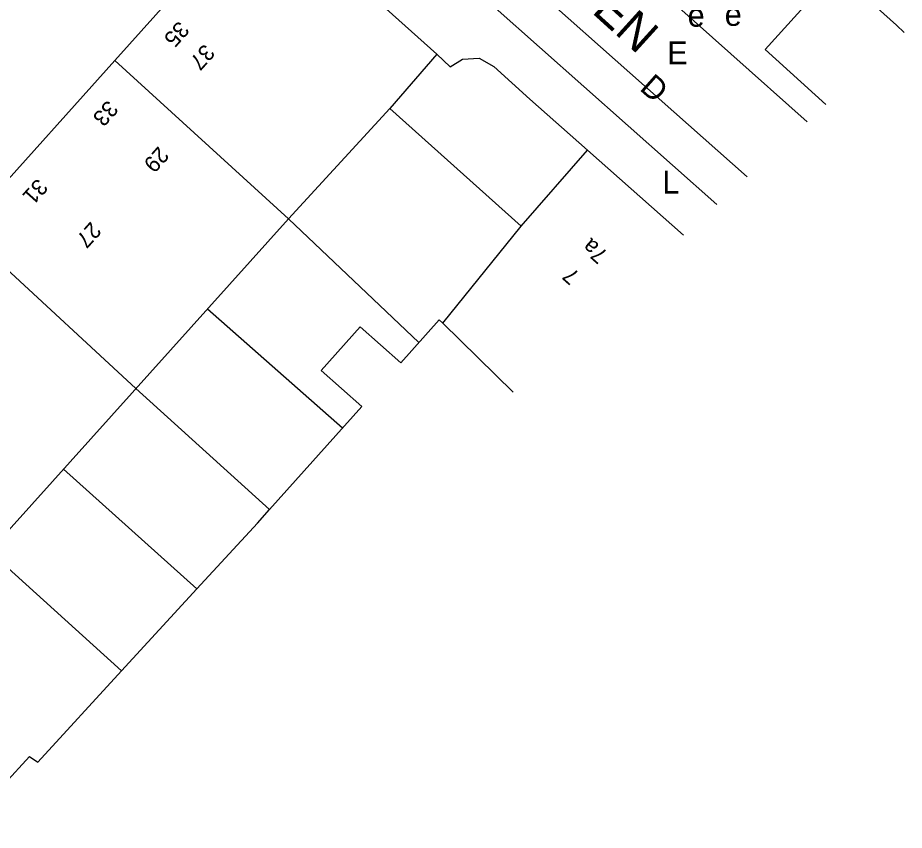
# Model space of a CAD drawing. Extents: x 81617 to 82144, y 454649 to 455150.
# Drawn here: x 81774.65 to 81813.36, y 454705.97 to 454741.45 of the extents above; entities that cross this region are included whole.
import ezdxf

# ---------------------------------------------------------------- set-up
doc = ezdxf.new("R2010")
doc.units = 0
doc.layers.add('B-WE-OG-TOPOGRAFIE-G', color=7, linetype='Continuous')

msp = doc.modelspace()

# ---------------------------------------------------------------- linework, layer by layer
at = {"layer": 'B-WE-OG-TOPOGRAFIE-G'}
for p, q in [((81786.184, 454745.913), (81792.953, 454739.866)), ((81778.882, 454739.59), (81786.471, 454732.664)), ((81796.628, 454732.35), (81790.902, 454737.492)), ((81786.471, 454732.664), (81792.167, 454727.273)), ((81772.269, 454732.218), (81779.806, 454725.258)), ((81788.823, 454723.533), (81782.927, 454728.726)), ((81793.212, 454728.117), (81796.283, 454725.103)), ((81779.806, 454725.258), (81785.644, 454719.976)), ((81776.641, 454721.741), (81782.472, 454716.506)), ((81779.184, 454712.926), (81773.413, 454718.154))]:
    msp.add_line(p, q, dxfattribs=at)
for points in [[(81748.534, 454720.978), (81757.717, 454731.089), (81778.088, 454753.354), (81778.662, 454754.017), (81780.035, 454755.151), (81781.627, 454755.951), (81783.357, 454756.378), (81785.138, 454756.409), (81786.881, 454756.043), (81788.5, 454755.298), (81789.912, 454754.212), (81794.189, 454750.346), (81795.928, 454748.775), (81799.634, 454745.418), (81802.448, 454742.866), (81809.12, 454736.913)], [(81792.274, 454747.121), (81791.119, 454745.863), (81793.559, 454743.623), (81805.182, 454733.29)], [(81806.5, 454734.502), (81792.274, 454747.121)], [(81773.211, 454733.271), (81778.882, 454739.59), (81784.127, 454745.433)], [(81810.388, 454743.502), (81807.294, 454740.065), (81809.936, 454737.664)], [(81810.388, 454743.502), (81813.017, 454741.129), (81813.362, 454740.815)], [(81792.953, 454739.866), (81790.902, 454737.492), (81786.471, 454732.664), (81770.094, 454714.466), (81766.995, 454710.894), (81768.568, 454709.482), (81768.466, 454709.313), (81769.411, 454708.558), (81772.299, 454705.967), (81774.071, 454708.001), (81775.156, 454709.186), (81775.527, 454708.939), (81779.184, 454712.926), (81782.472, 454716.506), (81785.115, 454719.385), (81785.644, 454719.976)], [(81792.953, 454739.866), (81793.528, 454739.311), (81794.067, 454739.649), (81794.802, 454739.681), (81795.444, 454739.321), (81797.013, 454737.904), (81799.534, 454735.669)], [(81785.644, 454719.976), (81789.668, 454724.478), (81787.903, 454726.045), (81789.601, 454727.959), (81791.374, 454726.386), (81793.048, 454728.258), (81793.212, 454728.117), (81796.628, 454732.35), (81799.534, 454735.669)], [(81799.534, 454735.669), (81803.727, 454731.952)]]:
    msp.add_lwpolyline(points, dxfattribs=at)

# ---------------------------------------------------------------- texts
for s, height, rotation, p in [('LAMGROEN', 1.5, 317.7716, (81793.24, 454747.536)), ('35', 0.7, 228.0759, (81781.679, 454741.349)), ('37', 0.7, 228.0759, (81782.796, 454740.347)), ('D', 1, 318.5682, (81801.763, 454738.323)), ('33', 0.7, 228.0759, (81778.575, 454737.891)), ('29', 0.7, 228.0759, (81780.795, 454735.875)), ('31', 0.7, 228.0759, (81775.505, 454734.473)), ('27', 0.7, 228.0759, (81777.839, 454732.582)), ('7a', 0.7, 138.4426, (81800.461, 454731.174)), ('7', 0.7, 138.4426, (81799.23, 454730.26))]:
    msp.add_text(s, height=height, rotation=rotation, dxfattribs=at).set_placement(p)
for s, p in [('e', (81803.901, 454741.062)), ('e', (81805.521, 454741.099)), ('E', (81803.013, 454739.418)), ('L', (81802.802, 454733.775))]:
    msp.add_text(s, height=1, dxfattribs=at).set_placement(p)

doc.saveas('drawing.dxf')
